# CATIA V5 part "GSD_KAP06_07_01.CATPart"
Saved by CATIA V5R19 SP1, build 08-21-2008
Part number: GSD_SWEEP_EXPLICIT
Definition: Beispielmodell für die Funktion Translation - Explizit / Sweep - Explicit.
Description: CATIA V5 Flächenmodellierung  Copyright (c) 2009 Maik Hertha IT Consultants
Bounding box of the stored display mesh (mm): x -101.319 to 149.034, y -56.522 to 1.371, z -3.561 to 24.497
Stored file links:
  \GSD_BUCH_UEBUNG\GSD_KAP06_07_01.CATPart
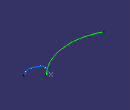
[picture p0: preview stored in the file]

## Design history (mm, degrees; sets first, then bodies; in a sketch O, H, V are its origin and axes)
AxisSystem1 "Absolute Axis System": origin (0, 0, 0), X (1, 0, 0), Y (0, 1, 0), Z (0, 0, 1)
Set1
  Sketch1 on XY plane of AxisSystem1, origin (0, 0, 0), H (1, 0, 0), V (0, 1, 0)
    spline S1 through (-84.4402, 28.3163) (-41.9975, 13.9992) (16.6726, -3.8633) (83.1477, 26.0664)
    arc A1 centre (-12.5654, 127.5678) radius 184.0903 from (-101.3193, -33.7146) to (113.7312, -6.3666) ccw
    point P2 (-101.3193, -33.7146)
    curve C1
    curve C2
    construction line L1 (113.7312, -6.3666) -> (68.543, 41.5543)
    construction line L2 (113.7312, -6.3666) -> (148.8891, 26.7864)
    construction line L3 (-84.4402, 28.3163) -> (-126.2849, 39.7026)
    point P6 (-84.4402, 28.3163)
    construction line L4 (-84.4402, 28.3163) -> (-102.8926, -39.4963)
    point P9 (83.1477, 26.0664)
    point P10 (-84.4402, 28.3163)
    perpendicularity: L2 L1, L4 L3
    tangency: A1 L2, L3 S1
    coincidence: L1 P9, P10 P6, P2 L4
  Plane1: type Normal, Curve Sketch1.C2, RefPoint {point type OnCurve, Support Sketch1.C1, Ratio 1}
  Sketch2 on Plane1, origin (113.7312, -6.3666, 0), H (0.6861, -0.7275, 0), V (0, 0, 1)
    point P1 (-10.6349, 0)
    line L1 (-10.6349, 0) -> (2.453, 19.9771)
    line L2 (13.2775, 24.1898) -> (34.8345, 18.7192)
    line L3 (47.2539, 7.6111) -> (51.4574, -3.5606)
    arc A1 centre (10.8177, 14.497) radius 10 from (2.453, 19.9771) to (13.2775, 24.1898) cw
    arc A2 centre (30.407, 1.2722) radius 18 from (34.8345, 18.7192) to (47.2539, 7.6111) cw
    curve C1
    line L4 (58.6057, -2.3035) -> (-22.3418, 21.9357)
    curve C2
    radius A2 = 18
    radius A1 = 10
    coincidence: P1 H
    tangency: A1 L1, A1 L2, A2 L2, A2 L3
  Point1: type OnCurve, Support Sketch2.C1, Ratio 1
  Point2: type OnCurve, Support Sketch2.C1, Ratio 0
Body1 (main body)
